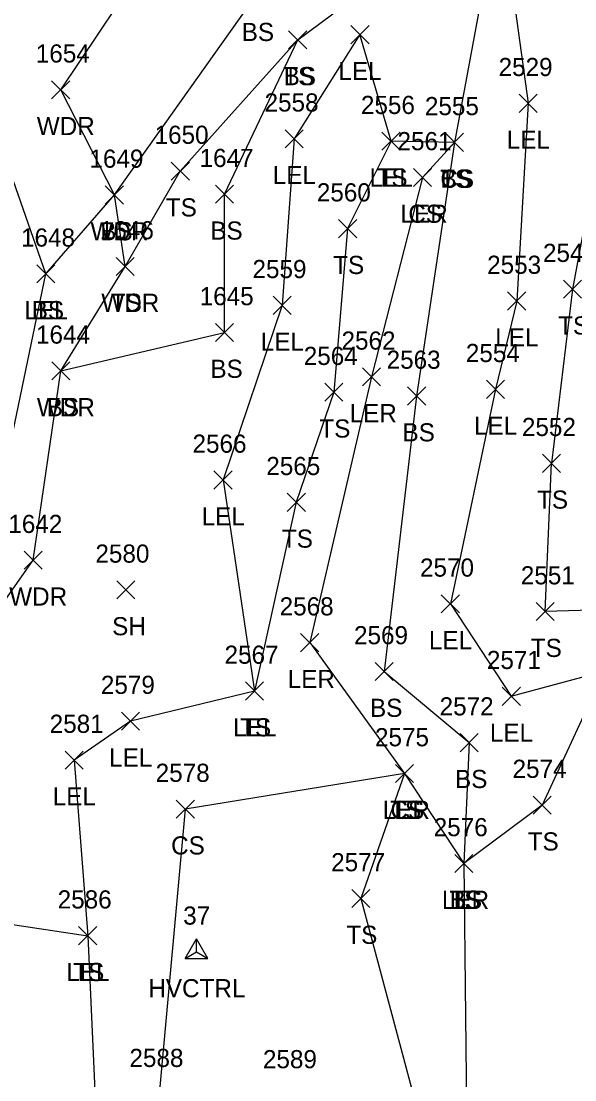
# Model space of a CAD drawing. Extents: x 1483143 to 1488182, y 802902 to 807581.
# Drawn here: x 1487711.4 to 1487772.4, y 805857.9 to 805974.5 of the extents above; entities that cross this region are included whole.
import ezdxf

# ---------------------------------------------------------------- set-up
doc = ezdxf.new("R2010")
doc.units = 0
for name, color, linetype in [('C_A', 7, 'Continuous'), ('C_I', 7, 'Continuous'), ('CPSM', 7, 'Continuous'), ('L_A', 7, 'Continuous'), ('L_I', 7, 'Continuous'), ('L_TIC', 7, 'Continuous'), ('LARO', 7, 'Continuous'), ('LAWA', 7, 'Continuous'), ('LELB', 7, 'Continuous')]:
    doc.layers.add(name, color=color, linetype=linetype)

msp = doc.modelspace()

# ---------------------------------------------------------------- linework, layer by layer
at = {"layer": 'CPSM'}
for p, q in [((1487729.46, 805871.24), (1487730.71, 805873.41)), ((1487731.96, 805871.24), (1487730.71, 805873.41)), ((1487730.71, 805871.96), (1487730.71, 805873.41)), ((1487729.46, 805871.24), (1487730.71, 805871.96)), ((1487730.71, 805871.96), (1487730.71, 805871.96)), ((1487730.71, 805871.96), (1487731.96, 805871.24)), ((1487729.46, 805871.24), (1487731.96, 805871.24))]:
    msp.add_line(p, q, dxfattribs=at)
at = {"layer": 'L_TIC'}
for points in [[(1487740.86, 805971.44), (1487742.86, 805973.44)], [(1487742.86, 805971.44), (1487740.86, 805973.44)], [(1487740.86, 805971.44), (1487742.86, 805973.44)], [(1487742.86, 805971.44), (1487740.86, 805973.44)], [(1487747.72, 805972.01), (1487749.72, 805974.01)], [(1487749.72, 805972.01), (1487747.72, 805974.01)], [(1487714.74, 805965.94), (1487716.74, 805967.94)], [(1487716.74, 805965.94), (1487714.74, 805967.94)], [(1487766.26, 805964.45), (1487768.26, 805966.45)], [(1487768.26, 805964.45), (1487766.26, 805966.45)], [(1487740.47, 805960.54), (1487742.47, 805962.54)], [(1487742.47, 805960.54), (1487740.47, 805962.54)], [(1487751.15, 805960.27), (1487753.15, 805962.27)], [(1487753.15, 805960.27), (1487751.15, 805962.27)], [(1487751.15, 805960.27), (1487753.15, 805962.27)], [(1487753.15, 805960.27), (1487751.15, 805962.27)], [(1487758.14, 805960.14), (1487760.14, 805962.14)], [(1487760.14, 805960.14), (1487758.14, 805962.14)], [(1487758.14, 805960.14), (1487760.14, 805962.14)], [(1487760.14, 805960.14), (1487758.14, 805962.14)], [(1487758.14, 805960.14), (1487760.14, 805962.14)], [(1487760.14, 805960.14), (1487758.14, 805962.14)], [(1487727.92, 805956.98), (1487729.92, 805958.98)], [(1487729.92, 805956.98), (1487727.92, 805958.98)], [(1487754.61, 805956.28), (1487756.61, 805958.28)], [(1487756.61, 805956.28), (1487754.61, 805958.28)], [(1487754.61, 805956.28), (1487756.61, 805958.28)], [(1487756.61, 805956.28), (1487754.61, 805958.28)], [(1487720.66, 805954.35), (1487722.66, 805956.35)], [(1487722.66, 805954.35), (1487720.66, 805956.35)], [(1487720.66, 805954.35), (1487722.66, 805956.35)], [(1487722.66, 805954.35), (1487720.66, 805956.35)], [(1487732.79, 805954.43), (1487734.79, 805956.43)], [(1487734.79, 805954.43), (1487732.79, 805956.43)], [(1487746.36, 805950.64), (1487748.36, 805952.64)], [(1487748.36, 805950.64), (1487746.36, 805952.64)], [(1487721.85, 805946.47), (1487723.85, 805948.47)], [(1487723.85, 805946.47), (1487721.85, 805948.47)], [(1487721.85, 805946.47), (1487723.85, 805948.47)], [(1487723.85, 805946.47), (1487721.85, 805948.47)], [(1487713.11, 805945.66), (1487715.11, 805947.66)], [(1487715.11, 805945.66), (1487713.11, 805947.66)], [(1487713.11, 805945.66), (1487715.11, 805947.66)], [(1487715.11, 805945.66), (1487713.11, 805947.66)], [(1487771.15, 805943.97), (1487773.15, 805945.97)], [(1487773.15, 805943.97), (1487771.15, 805945.97)], [(1487765, 805942.66), (1487767, 805944.66)], [(1487767, 805942.66), (1487765, 805944.66)], [(1487739.15, 805942.19), (1487741.15, 805944.19)], [(1487741.15, 805942.19), (1487739.15, 805944.19)], [(1487732.8, 805939.2), (1487734.8, 805941.2)], [(1487734.8, 805939.2), (1487732.8, 805941.2)], [(1487714.76, 805934.97), (1487716.76, 805936.97)], [(1487716.76, 805934.97), (1487714.76, 805936.97)], [(1487714.76, 805934.97), (1487716.76, 805936.97)], [(1487716.76, 805934.97), (1487714.76, 805936.97)], [(1487749, 805934.31), (1487751, 805936.31)], [(1487751, 805934.31), (1487749, 805936.31)], [(1487762.65, 805932.94), (1487764.65, 805934.94)], [(1487764.65, 805932.94), (1487762.65, 805934.94)], [(1487744.84, 805932.62), (1487746.84, 805934.62)], [(1487746.84, 805932.62), (1487744.84, 805934.62)], [(1487753.97, 805932.2), (1487755.97, 805934.2)], [(1487755.97, 805932.2), (1487753.97, 805934.2)], [(1487768.83, 805924.79), (1487770.83, 805926.79)], [(1487770.83, 805924.79), (1487768.83, 805926.79)], [(1487768.83, 805924.79), (1487770.83, 805926.79)], [(1487770.83, 805924.79), (1487768.83, 805926.79)], [(1487732.63, 805922.95), (1487734.63, 805924.95)], [(1487734.63, 805922.95), (1487732.63, 805924.95)], [(1487740.71, 805920.49), (1487742.71, 805922.49)], [(1487742.71, 805920.49), (1487740.71, 805922.49)], [(1487711.71, 805914.11), (1487713.71, 805916.11)], [(1487713.71, 805914.11), (1487711.71, 805916.11)], [(1487721.92, 805910.84), (1487723.92, 805912.84)], [(1487723.92, 805910.84), (1487721.92, 805912.84)], [(1487757.69, 805909.3), (1487759.69, 805911.3)], [(1487759.69, 805909.3), (1487757.69, 805911.3)], [(1487768.14, 805908.45), (1487770.14, 805910.45)], [(1487770.14, 805908.45), (1487768.14, 805910.45)], [(1487742.18, 805905.03), (1487744.18, 805907.03)], [(1487744.18, 805905.03), (1487742.18, 805907.03)], [(1487750.38, 805901.85), (1487752.38, 805903.85)], [(1487752.38, 805901.85), (1487750.38, 805903.85)], [(1487736.11, 805899.7), (1487738.11, 805901.7)], [(1487738.11, 805899.7), (1487736.11, 805901.7)], [(1487736.11, 805899.7), (1487738.11, 805901.7)], [(1487738.11, 805899.7), (1487736.11, 805901.7)], [(1487764.4, 805899.12), (1487766.4, 805901.12)], [(1487766.4, 805899.12), (1487764.4, 805901.12)], [(1487722.44, 805896.38), (1487724.44, 805898.38)], [(1487724.44, 805896.38), (1487722.44, 805898.38)], [(1487759.76, 805894.01), (1487761.76, 805896.01)], [(1487761.76, 805894.01), (1487759.76, 805896.01)], [(1487716.22, 805892.09), (1487718.22, 805894.09)], [(1487718.22, 805892.09), (1487716.22, 805894.09)], [(1487716.22, 805892.09), (1487718.22, 805894.09)], [(1487718.22, 805892.09), (1487716.22, 805894.09)], [(1487752.64, 805890.61), (1487754.64, 805892.61)], [(1487754.64, 805890.61), (1487752.64, 805892.61)], [(1487752.64, 805890.61), (1487754.64, 805892.61)], [(1487754.64, 805890.61), (1487752.64, 805892.61)], [(1487752.64, 805890.61), (1487754.64, 805892.61)], [(1487754.64, 805890.61), (1487752.64, 805892.61)], [(1487728.47, 805886.69), (1487730.47, 805888.69)], [(1487730.47, 805886.69), (1487728.47, 805888.69)], [(1487767.8, 805887.13), (1487769.8, 805889.13)], [(1487769.8, 805887.13), (1487767.8, 805889.13)], [(1487759.17, 805880.7), (1487761.17, 805882.7)], [(1487761.17, 805880.7), (1487759.17, 805882.7)], [(1487759.17, 805880.7), (1487761.17, 805882.7)], [(1487761.17, 805880.7), (1487759.17, 805882.7)], [(1487759.17, 805880.7), (1487761.17, 805882.7)], [(1487761.17, 805880.7), (1487759.17, 805882.7)], [(1487747.81, 805876.84), (1487749.81, 805878.84)], [(1487749.81, 805876.84), (1487747.81, 805878.84)], [(1487717.72, 805872.74), (1487719.72, 805874.74)], [(1487719.72, 805872.74), (1487717.72, 805874.74)], [(1487717.72, 805872.74), (1487719.72, 805874.74)], [(1487719.72, 805872.74), (1487717.72, 805874.74)]]:
    msp.add_lwpolyline(points, dxfattribs=at)
at = {"layer": 'LARO'}
for points in [[(1487840.18, 806185.42), (1487834.67, 806182.6), (1487822.58, 806178.25), (1487811.01, 806152.68), (1487805.8, 806138.73), (1487805.57, 806125.09), (1487812.67, 806122.39), (1487808.76, 806106.51), (1487799.94, 806095.08), (1487791.75, 806069.31), (1487789.16, 806039.67), (1487787.77, 806021.85), (1487782.39, 806010.38), (1487772.44, 806000.5), (1487764.14, 805988.07), (1487767.26, 805965.45), (1487766, 805943.66), (1487763.65, 805933.94), (1487758.69, 805910.3), (1487765.4, 805900.12), (1487775.65, 805902.89)], [(1487519.52, 805604.85), (1487528.65, 805619.18), (1487533.33, 805631.91), (1487543.2, 805654.53), (1487555.05, 805678.36), (1487574.29, 805702.91), (1487587.86, 805730.92), (1487594.38, 805745.99), (1487602.81, 805747.66), (1487615.34, 805754.21), (1487619.89, 805765.57), (1487618.06, 805788.02), (1487632.01, 805808.09), (1487647.52, 805827.2), (1487662.05, 805847.87), (1487673.84, 805865.59), (1487680.96, 805879.63), (1487690.31, 805890.08), (1487695.82, 805899.7), (1487708.05, 805917.66), (1487714.11, 805946.66), (1487707.45, 805965.6), (1487711.43, 805989.94)], [(1487752.15, 805961.27), (1487748.72, 805973.01), (1487741.47, 805961.54), (1487740.15, 805943.19), (1487733.63, 805923.95), (1487737.11, 805900.7), (1487723.44, 805897.38), (1487717.22, 805893.09), (1487718.72, 805873.74), (1487719.68, 805852.62), (1487715.13, 805841.65)], [(1487755.61, 805957.28), (1487750, 805935.31), (1487743.18, 805906.03), (1487753.64, 805891.61), (1487760.17, 805881.7), (1487760.52, 805848.06), (1487753.92, 805823.19), (1487741.47, 805808.79), (1487734.22, 805791.56), (1487719.18, 805781.13), (1487716.6, 805787.44), (1487716.46, 805794.77), (1487719.6, 805807.63), (1487722.39, 805826.57), (1487717.66, 805837.02), (1487715.13, 805841.65)]]:
    msp.add_lwpolyline(points, dxfattribs=at)
at = {"layer": 'LAWA'}
msp.add_lwpolyline([(1487529.09, 805606.14), (1487539.28, 805632.42), (1487550.45, 805657.72), (1487555.05, 805678.36), (1487580.53, 805701.65), (1487594.42, 805727.14), (1487615.34, 805754.21), (1487623.26, 805766.5), (1487630.87, 805783.06), (1487637.96, 805804.22), (1487654.61, 805825.46), (1487661.73, 805840.49), (1487675.69, 805864.29), (1487683.26, 805876.52), (1487690.31, 805890.08), (1487698.57, 805894.98), (1487712.71, 805915.11), (1487715.76, 805935.97), (1487722.85, 805947.47), (1487721.66, 805955.35), (1487715.74, 805966.94), (1487726.15, 805982.46)], dxfattribs=at)
at = {"layer": 'LELB'}
for points in [[(1487722.85, 805947.47), (1487728.92, 805957.98), (1487741.86, 805972.44), (1487759.45, 805985.51), (1487774.65, 806014.13), (1487785.01, 806040.02), (1487783.16, 806085.43), (1487789.38, 806109.3)], [(1487714.11, 805946.66), (1487721.66, 805955.35), (1487737.25, 805977.31), (1487756.23, 805993.29), (1487766.26, 806020.25), (1487776.49, 806046.35), (1487776.28, 806087.32)], [(1487791.75, 806069.31), (1487800.5, 806057.87), (1487800.39, 806042.54), (1487800.48, 806025.16), (1487789.32, 806004.69), (1487784.57, 805996.75), (1487778.77, 805994.85), (1487776.59, 805983.59), (1487777.73, 805968.72), (1487775.54, 805963.15), (1487772.15, 805944.97), (1487769.83, 805925.79)], [(1487764.14, 805988.07), (1487759.14, 805961.14), (1487754.97, 805933.2), (1487751.38, 805902.85), (1487760.76, 805895.01), (1487760.17, 805881.7)], [(1487715.76, 805935.97), (1487733.8, 805940.2), (1487733.79, 805955.43), (1487741.86, 805972.44)], [(1487794.56, 805961.86), (1487795.32, 805942.18), (1487790.3, 805931.28), (1487787.61, 805918.4), (1487781.94, 805909.82), (1487769.14, 805909.45), (1487769.83, 805925.79)], [(1487759.14, 805961.14), (1487752.15, 805961.27), (1487747.36, 805951.64), (1487745.84, 805933.62), (1487741.71, 805921.49), (1487737.11, 805900.7)], [(1487759.14, 805961.14), (1487755.61, 805957.28)], [(1487775.65, 805902.89), (1487768.8, 805888.13), (1487760.17, 805881.7)], [(1487695.87, 805891.2), (1487704.06, 805875.92), (1487718.72, 805873.74)], [(1487753.64, 805891.61), (1487729.47, 805887.69), (1487726.58, 805856.28), (1487731.51, 805838.07), (1487735.96, 805829.79), (1487729.12, 805794.58), (1487720.74, 805793.59), (1487716.6, 805787.44)], [(1487753.64, 805891.61), (1487748.81, 805877.84), (1487756.11, 805850.63), (1487748.35, 805842.75), (1487742.63, 805828.05), (1487741.47, 805808.79)]]:
    msp.add_lwpolyline(points, dxfattribs=at)

# ---------------------------------------------------------------- texts
at = {"layer": 'C_A'}
msp.add_text('HVCTRL', height=2, dxfattribs=at).set_placement((1487725.4, 805866.96))
at = {"layer": 'C_I'}
msp.add_text('37', height=2, dxfattribs=at).set_placement((1487729.24, 805874.96))
at = {"layer": 'L_A'}
for s, p in [('BS', (1487735.69, 805972.31)), ('LEL', (1487746.35, 805968.01)), ('TS', (1487740.27, 805967.44)), ('BS', (1487740.31, 805967.44)), ('WDR', (1487713.11, 805961.94)), ('LEL', (1487764.9, 805960.45)), ('LEL', (1487739.11, 805956.54)), ('LEL', (1487749.78, 805956.27)), ('TS', (1487750.55, 805956.27)), ('TS', (1487757.55, 805956.14)), ('CS', (1487757.58, 805956.14)), ('BS', (1487757.58, 805956.14)), ('TS', (1487727.33, 805952.98)), ('LER', (1487753.19, 805952.28)), ('CS', (1487754.05, 805952.28)), ('BS', (1487732.23, 805950.43)), ('WDR', (1487719.02, 805950.35)), ('BS', (1487720.1, 805950.35)), ('TS', (1487745.77, 805946.64)), ('WDR', (1487720.22, 805942.47)), ('TS', (1487721.26, 805942.47)), ('LEL', (1487711.75, 805941.66)), ('BS', (1487712.55, 805941.66)), ('TS', (1487770.56, 805939.97)), ('LEL', (1487737.79, 805938.19)), ('LEL', (1487763.63, 805938.66)), ('BS', (1487732.24, 805935.2)), ('WDR', (1487713.12, 805930.97)), ('BS', (1487714.2, 805930.97)), ('LER', (1487747.58, 805930.31)), ('TS', (1487744.25, 805928.62)), ('LEL', (1487761.29, 805928.94)), ('BS', (1487753.41, 805928.2)), ('TS', (1487768.24, 805920.79)), ('TS', (1487768.24, 805920.79)), ('LEL', (1487731.27, 805918.95)), ('TS', (1487740.12, 805916.49)), ('WDR', (1487710.07, 805910.11)), ('SH', (1487721.41, 805906.84)), ('LEL', (1487756.32, 805905.3)), ('TS', (1487767.55, 805904.45)), ('LER', (1487740.76, 805901.03)), ('BS', (1487749.83, 805897.85)), ('LEL', (1487734.75, 805895.7)), ('TS', (1487735.52, 805895.7)), ('LEL', (1487763.04, 805895.12)), ('LEL', (1487721.08, 805892.38)), ('BS', (1487759.2, 805890.01)), ('LEL', (1487714.86, 805888.09)), ('LEL', (1487714.86, 805888.09)), ('LER', (1487751.22, 805886.61)), ('TS', (1487752.05, 805886.61)), ('CS', (1487752.08, 805886.61)), ('TS', (1487767.21, 805883.13)), ('CS', (1487727.91, 805882.69)), ('LER', (1487757.75, 805876.7)), ('TS', (1487758.58, 805876.7)), ('BS', (1487758.61, 805876.7)), ('TS', (1487747.22, 805872.84)), ('TS', (1487717.13, 805868.74)), ('LEL', (1487716.36, 805868.74))]:
    msp.add_text(s, height=2, dxfattribs=at).set_placement(p)
at = {"layer": 'L_I'}
for s, p in [('1654', (1487713, 805969.94)), ('2529', (1487764, 805968.45)), ('2558', (1487738.21, 805964.54)), ('2556', (1487748.83, 805964.27)), ('2556', (1487748.83, 805964.27)), ('2555', (1487755.88, 805964.14)), ('2555', (1487755.88, 805964.14)), ('2555', (1487755.88, 805964.14)), ('1650', (1487726.09, 805960.98)), ('2561', (1487752.86, 805960.28)), ('2561', (1487752.86, 805960.28)), ('1649', (1487718.91, 805958.35)), ('1649', (1487718.91, 805958.35)), ('1647', (1487731.05, 805958.43)), ('2560', (1487743.97, 805954.64)), ('1646', (1487720.06, 805950.47)), ('1646', (1487720.06, 805950.47)), ('1648', (1487711.37, 805949.66)), ('1648', (1487711.37, 805949.66)), ('2545', (1487768.89, 805947.97)), ('2559', (1487736.88, 805946.19)), ('2553', (1487762.74, 805946.66)), ('1645', (1487731.06, 805943.2)), ('1644', (1487713.02, 805938.97)), ('1644', (1487713.02, 805938.97)), ('2562', (1487746.69, 805938.31)), ('2564', (1487742.53, 805936.62)), ('2554', (1487760.39, 805936.94)), ('2563', (1487751.66, 805936.2)), ('2552', (1487766.57, 805928.79)), ('2552', (1487766.57, 805928.79)), ('2566', (1487730.27, 805926.95)), ('2565', (1487738.4, 805924.49)), ('1642', (1487709.97, 805918.11)), ('2580', (1487719.57, 805914.84)), ('2570', (1487755.34, 805913.3)), ('2551', (1487766.45, 805912.45)), ('2568', (1487739.87, 805909.03)), ('2569', (1487748.07, 805905.85)), ('2567', (1487733.8, 805903.7)), ('2567', (1487733.8, 805903.7)), ('2571', (1487762.71, 805903.12)), ('2579', (1487720.17, 805900.38)), ('2572', (1487757.5, 805898.01)), ('2581', (1487714.53, 805896.09)), ('2581', (1487714.53, 805896.09)), ('2575', (1487750.38, 805894.61)), ('2575', (1487750.38, 805894.61)), ('2575', (1487750.38, 805894.61)), ('2574', (1487765.54, 805891.13)), ('2578', (1487726.21, 805890.69)), ('2576', (1487756.85, 805884.7)), ('2576', (1487756.85, 805884.7)), ('2576', (1487756.85, 805884.7)), ('2577', (1487745.55, 805880.84)), ('2586', (1487715.41, 805876.74)), ('2586', (1487715.41, 805876.74)), ('2588', (1487723.32, 805859.28)), ('2589', (1487738.03, 805859.14))]:
    msp.add_text(s, height=2, dxfattribs=at).set_placement(p)

doc.saveas('drawing.dxf')
